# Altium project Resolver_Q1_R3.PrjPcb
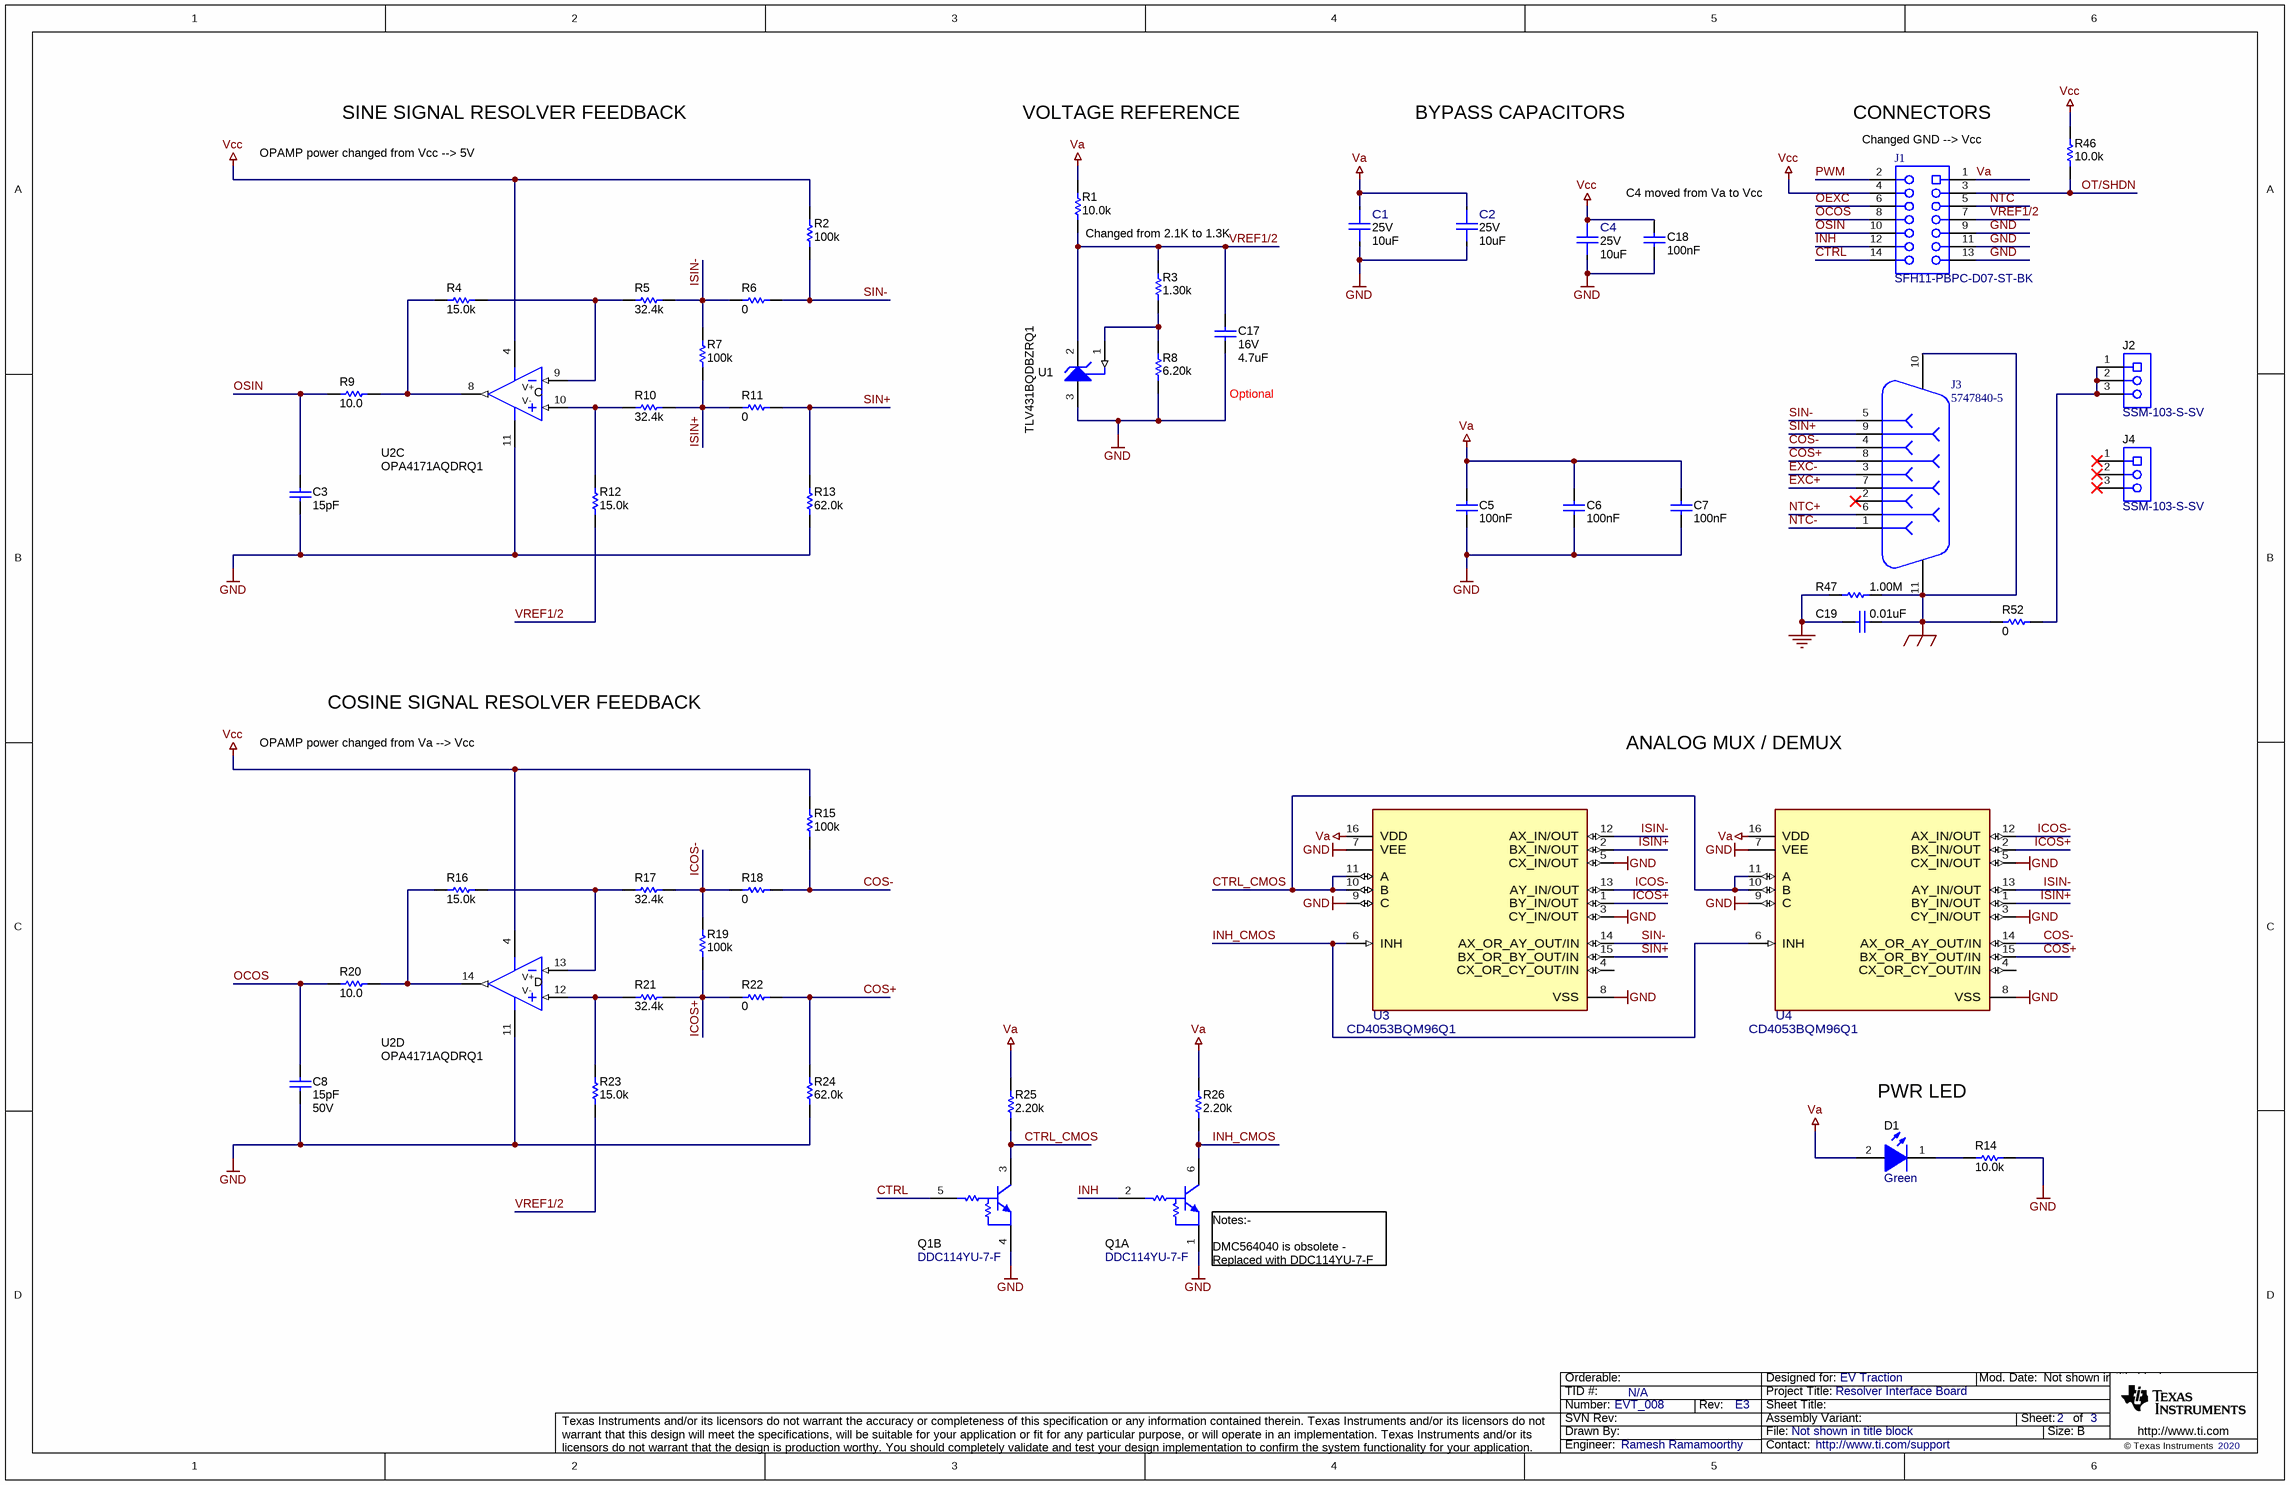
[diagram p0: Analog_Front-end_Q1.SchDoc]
CopyrightYear: 2020; PCB_Layout: Ramesh Ramamoorthy; PCB_Rev: E3; PRJ_Customer: EV Traction; PRJ_Engineer: Ramesh Ramamoorthy; PRJ_Number: EVT_008; PRJ_Title: Resolver Interface Board; SCH_Rev: E3; TechSupport: http://www.ti.com/support; TID: N/A
2 sheets, 102 parts. Net scope: global (net labels, ports and power ports of the same name join across sheets).
Board file: Resolver_Q1_R3.PcbDoc
Sheets:
  Analog_Front-end_Q1.SchDoc
  Excitation_Amplifier.SchDoc

## Sheet Analog_Front-end_Q1.SchDoc
size 431 x 279 mm; Date: Not shown in title block; ApprovedBy: Not shown in title block; CheckedBy: Not shown in title block; Author: Not shown in title block; CompanyName: Not shown in title block; Engineer: Not shown in title block; Organization: Not shown in title block; Address1: Not shown in title block; Address2: Not shown in title block; Address3: Not shown in title block; Address4: Not shown in title block; DocumentNumber: 2; Revision: Use project parameter SCH_Rev; SheetNumber: 2; SheetTotal: 3; PageSetup: Record=PageOptions¦CenterHorizontal=True¦CenterVertical=True¦PrintScale=1.00¦XCorrection=1.00¦YCorrection=1.00¦PrintKind=0¦BorderSize=5000000¦LeftOffset=0¦BottomOffset=0¦Orientation=2¦PaperLength=1000¦PaperWidth=1000¦Scale=100¦PaperSource=15¦PrintQuality=600¦MediaType=1¦DitherType=10¦PaperKind=Letter¦PrintScaleMode=1

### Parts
C1  VDC_V: 25V  ValueDisplayed: 10uF  [FP-CGA4J1X7S1E106K125AC_0805-MFG]  (hidden comment: CGA4J1X7S1E106K125AC)
C2  VDC_V: 25V  ValueDisplayed: 10uF  [FP-CGA4J1X7S1E106K125AC_0805-MFG]  (hidden comment: CGA4J1X7S1E106K125AC)
C3  ValueDisplayed: 15pF  [0603_HV]  (hidden comment: GRM1885C1H150JA01D)
C4  VDC_V: 25V  ValueDisplayed: 10uF  [FP-CGA4J1X7S1E106K125AC_0805-MFG]  (hidden comment: CGA4J1X7S1E106K125AC)
C5  Cap_F: 100nF  [0603_HV]  (hidden comment: GRM188R71E104KA01D)
C6  Cap_F: 100nF  [0603_HV]  (hidden comment: GRM188R71E104KA01D)
C7  Cap_F: 100nF  [0603_HV]  (hidden comment: GRM188R71E104KA01D)
C8  ValueDisplayed: 15pF  VDC_V: 50V  [0603_HV]  (hidden comment: GRM1885C1H150JA01D)
C17  VDC_V: 16V  ValueDisplayed: 4.7uF  [0603_HV]  (hidden comment: C1608X6S1C475K080AC)
C18  Cap_F: 100nF  [0603_HV]  (hidden comment: GRM188R71E104KA01D)
C19  ValueDisplayed: 0.01uF  [1206]  (hidden comment: 12061C103JAT2A)
D1  value Green  [WL-SMCW_GREEN]  (hidden comment: 150060GS75000)
J1  SFH11-PBPC-D07-ST-BK  [Sullins_SFH11-xxxC-D07-ST-BK]
J2  SSM-103-S-SV  [Samtec_SSM-103-x-SV]
J3  5747840-5  [TE_5747840-5]
J4  SSM-103-S-SV  [Samtec_SSM-103-x-SV]
Q1  DDC114YU-7-F  [SOT-363]  (parts A,B of 2)
R1  ValueDisplayed: 10.0k  [0603_HV]  (hidden comment: RC0603FR-0710KL)
R2  ValueDisplayed: 100k  [0603_HV]  (hidden comment: RC0603FR-07100KL)
R3  ValueDisplayed: 1.30k  [0603_HV]  (hidden comment: RC0603FR-071K3L)
R4  ValueDisplayed: 15.0k  [0603_HV]  (hidden comment: RC0603FR-0715KL)
R5  ValueDisplayed: 32.4k  [0603_HV]  (hidden comment: RC0603FR-0732K4L)
R6  ValueDisplayed: 0  [0603_HV]  (hidden comment: RC0603JR-070RL)
R7  ValueDisplayed: 100k  [0603_HV]  (hidden comment: RC0603FR-07100KL)
R8  ValueDisplayed: 6.20k  [0603_HV]  (hidden comment: RC0603FR-076K2L)
R9  ValueDisplayed: 10.0  [0603_HV]  (hidden comment: RC0603FR-0710RL)
R10  ValueDisplayed: 32.4k  [0603_HV]  (hidden comment: RC0603FR-0732K4L)
R11  ValueDisplayed: 0  [0603_HV]  (hidden comment: RC0603JR-070RL)
R12  ValueDisplayed: 15.0k  [0603_HV]  (hidden comment: RC0603FR-0715KL)
R13  ValueDisplayed: 62.0k  [0603_HV]  (hidden comment: RC0603FR-0762KL)
R14  ValueDisplayed: 10.0k  [0603_HV]  (hidden comment: RC0603FR-0710KL)
R15  ValueDisplayed: 100k  [0603_HV]  (hidden comment: RC0603FR-07100KL)
R16  ValueDisplayed: 15.0k  [0603_HV]  (hidden comment: RC0603FR-0715KL)
R17  ValueDisplayed: 32.4k  [0603_HV]  (hidden comment: RC0603FR-0732K4L)
R18  ValueDisplayed: 0  [0603_HV]  (hidden comment: RC0603JR-070RL)
R19  ValueDisplayed: 100k  [0603_HV]  (hidden comment: RC0603FR-07100KL)
R20  ValueDisplayed: 10.0  [0603_HV]  (hidden comment: RC0603FR-0710RL)
R21  ValueDisplayed: 32.4k  [0603_HV]  (hidden comment: RC0603FR-0732K4L)
R22  ValueDisplayed: 0  [0603_HV]  (hidden comment: RC0603JR-070RL)
R23  ValueDisplayed: 15.0k  [0603_HV]  (hidden comment: RC0603FR-0715KL)
R24  ValueDisplayed: 62.0k  [0603_HV]  (hidden comment: RC0603FR-0762KL)
R25  ValueDisplayed: 2.20k  [0603_HV]  (hidden comment: RC0603FR-072K2L)
R26  ValueDisplayed: 2.20k  [0603_HV]  (hidden comment: RC0603FR-072K2L)
R46  ValueDisplayed: 10.0k  [0603_HV]  (hidden comment: RC0603FR-0710KL)
R47  ValueDisplayed: 1.00M  [0402S]  (hidden comment: ERJ-2RKF1004X)
R52  ValueDisplayed: 0  [0603_HV]  (hidden comment: RC0603JR-070RL)
U1  TLV431BQDBZRQ1  [DBZ0003A_N]
U2  OPA4171AQDRQ1  [D0014A_L]  (parts C,D of 4)
U3  CD4053BQM96Q1  [D0016A-MFG]
U4  CD4053BQM96Q1  [D0016A-MFG]

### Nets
GND: C1.2 C2.2 C3.1 C4.2 C5.1 C6.1 C7.1 C8.1 C17.2 C18.1 C19.2 J1.9 J1.11 J1.13 Q1.1(E) Q1.4(E) R8.1 R13.1 R14.1 R24.1 R47.1 U1.3(ANODE) U2.11(V-) U3.3(CY_IN/OUT) U3.5(CX_IN/OUT) U3.7(VEE) U3.8(VSS) U3.9(C) U4.3(CY_IN/OUT) U4.5(CX_IN/OUT) U4.7(VEE) U4.8(VSS) U4.9(C)
SHIELD_GND: C19.1 J3.10 J3.11 R47.2 R52.2
Va: C1.1 C2.1 C5.2 C6.2 C7.2 D1.2(A) J1.1 R1.2 R25.2 R26.2 U3.16(VDD) U4.16(VDD)
Vcc: C4.1 C18.2 J1.4 R2.2 R15.2 R46.2 U2.4(V+)
COS+: J3.8 R22.1 R24.2 U4.15(BX_OR_BY_OUT/IN)
COS-: J3.4 R15.1 R18.1 U4.14(AX_OR_AY_OUT/IN)
CTRL: J1.14 Q1.5(B)
CTRL_CMOS: Q1.3(C) R25.1 U3.10(B) U3.11(A) U4.10(B) U4.11(A)
EXC+: J3.7
EXC-: J3.3
ICOS+: R19.1 R21.1 R22.2 U3.1(BY_IN/OUT) U4.2(BX_IN/OUT)
ICOS-: R17.1 R18.2 R19.2 U3.13(AY_IN/OUT) U4.12(AX_IN/OUT)
INH: J1.12 Q1.2(B)
INH_CMOS: Q1.6(C) R26.1 U3.6(INH) U4.6(INH)
ISIN+: R7.1 R10.1 R11.2 U3.2(BX_IN/OUT) U4.1(BY_IN/OUT)
ISIN-: R5.1 R6.2 R7.2 U3.12(AX_IN/OUT) U4.13(AY_IN/OUT)
NTC: J1.5
NTC+: J3.6
NTC-: J3.1
OCOS: C8.2 J1.8 R20.2
OEXC: J1.6
OSIN: C3.2 J1.10 R9.2
OT/SHDN: J1.3 R46.1
PWM: J1.2
SIN+: J3.9 R11.1 R13.2 U3.15(BX_OR_BY_OUT/IN)
SIN-: J3.5 R2.1 R6.1 U3.14(AX_OR_AY_OUT/IN)
VREF1/2: C17.1 J1.7 R1.1 R3.2 R12.1 R23.1 U1.2(CATHODE)
NetD1_1: D1.1(K) R14.2
NetJ2_1: J2.1 J2.2 J2.3 R52.1
NetR3_1: R3.1 R8.2 U1.1(REF)
NetR4_1: R4.1 R5.2 U2.9(IN-)
NetR4_2: R4.2 R9.1 U2.8(OUT)
NetR10_2: R10.2 R12.2 U2.10(IN+)
NetR16_1: R16.1 R17.2 U2.13(IN-)
NetR16_2: R16.2 R20.1 U2.14(OUT)
NetR21_2: R21.2 R23.2 U2.12(IN+)

Not connected (* = marked no-connect by the designer): J3 2*; J4 1* 2* 3*; U3 4(CX_OR_CY_OUT/IN); U4 4(CX_OR_CY_OUT/IN)

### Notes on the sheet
- OPAMP power changed from Vcc --> 5V
- SINE SIGNAL RESOLVER FEEDBACK
- VOLTAGE REFERENCE
- BYPASS CAPACITORS
- CONNECTORS
- (near J1) Changed GND --> Vcc
- (near R1) Changed from 2.1K to 1.3K
- C4 moved from Va to Vcc
- Optional
- COSINE SIGNAL RESOLVER FEEDBACK
- OPAMP power changed from Va --> Vcc
- ANALOG MUX / DEMUX
- PWR LED
- (near Q1) Notes:-
  DMC564040 is obsolete -
  Replaced with DDC114YU-7-F

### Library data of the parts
C1 C2 C4 = CMP-0091069-1: Cap Ceramic 10uF 25V X7S 10% Pad SMD 0805 +125°C Automotive T/R; Manufacturer: TDK Corporation; AEC Qualified: Yes; AEC Grade: Grade 1; Value: 10µF; Tolerance_%: 0.1%; SizeZ_mm: 1.45mm; TempCo: 22%
C3 = CMP-0007184-4: CAP, CERM, 15 pF, 50 V, +/- 5%, C0G/NP0, 0603; Manufacturer: MuRata; Polarized: N; Value: 15pF; U/M: EA; Value1: Unknown; VDC_V: 50V; TaMin_C: -55°C; TaMax_C: 125°C; Cap_Case: 0603; AEC Category: Q200; SizeArea_mm2: 1.28; SizeAreaWB_mm2: 4.68; SizeX_mm: 1.6; SizeY_mm: 0.8; SizeZ_mm: 1
C5-C7 C18 = CMP-0007404-4: CAP, CERM, 0.1 uF, 25 V, +/- 10%, X7R, 0603; Manufacturer: MuRata; Polarized: N; Value: 0.1uF; U/M: EA; Value1: Unknown; VDC_V: 25V; TaMin_C: -55°C; TaMax_C: 125°C; Cap_Case: 0603; AEC Category: Q200; SizeArea_mm2: 1.28; SizeAreaWB_mm2: 4.68; SizeX_mm: 1.6; SizeY_mm: 0.8; SizeZ_mm: 1
C8 = CMP-0007184-4: CAP, CERM, 15 pF, 50 V, +/- 5%, C0G/NP0, 0603; Manufacturer: MuRata; Polarized: N; Value: 15pF; U/M: EA; Value1: Unknown; TaMin_C: -55°C; TaMax_C: 125°C; Cap_Case: 0603; AEC Category: Q200; SizeArea_mm2: 1.28; SizeAreaWB_mm2: 4.68; SizeX_mm: 1.6; SizeY_mm: 0.8; SizeZ_mm: 1
C17 = CMP-0007028-3: CAP, CERM, 4.7 uF, 16 V, +/- 10%, X6S, 0603; Manufacturer: TDK; TaMin_C: -55°C; ESR_ohm: 3.728m; Polarized: N; SizeAreaWB_mm2: 4.68; Value1: 0.003728 ohm; U/M: EA; Value: 4.7uF; TaMax_C: 105°C; SizeZ_mm: 1; SizeX_mm: 1.6; SizeY_mm: 0.8; Cap_Case: 0603; SizeArea_mm2: 1.28; Cap_F: 4.7µF; IRMS_A: 2.69359A; AEC Category: Q200
C19 = CMP-0008484-2: CAP, CERM, 0.01 uF, 100 V, +/- 5%, X7R, 1206; Manufacturer: AVX; TaMin_C: -55°C; ESR_ohm: 1.19d; Polarized: N; SizeAreaWB_mm2: 10.92; Value1: 0.119 ohm; U/M: EA; Value: 0.01uF; TaMax_C: 125°C; SizeZ_mm: 1.35; SizeX_mm: 3.2; SizeY_mm: 1.6; Value2: 100V; SizeArea_mm2: 5.12; Cap_F: 10nF; AEC Category: Q200
D1 = CMP-0002905-2: LED, Green, SMD; Manufacturer: Wurth Elektronik; Type: InGaN; Vf_V: 3.2V; Io_A: 20mA; Tjmax_C: 85°C; Value1: W; Angle: 140
J1 = CMP-0054668-1: Receptacle, 2.54mm, 7x2, Gold, Black, TH; Manufacturer: Sullins Connector Solutions; CNHeader: FALSE; Current_A: 3A; Gender: Female; Voltage_V: 1kV; CompType: Socket Strip; Row_Count: 2; RowSpacing_mm: 2.54; CT: TRUE; Cert_UL: Y
J2 J4 = CMP-0078183-1: Receptacle, 2.54mm, 3x1, Gold with Tin tail, SMT; Manufacturer: Samtec; Pitch_mm: 2.54; Gender: Female; Cert_CSA: Y; Voltage_V: 405V; Current_A: 5.2A; Row_Count: 1; CompType: Socket Strip
J3 = CMP-0054938-2: D-Sub, 2.74mm, 9 Position, R/A, TH; Manufacturer: TE Connectivity; CNHeader: FALSE; Gender: Male; Row_Count: 2; Pitch_mm: 2.74; ContactFinish: Gold; CT: TRUE; Cert_UL: Y
Q1 = CMP-0000496-2: Transistor, Dual NPN, 50 V, 0.1 A, SOT-363; Manufacturer: Panasonic; PNP: 0; NPN: 2; Vceo_V: 50V; Vcesat1_V: 250mV; Value: 50 V; IcRated_A: 100mA; Value1: 0.1 A; TaMin_C: -40°C; TaMax_C: 85°C; SizeAreaWB_mm2: 10.24; SizeArea_mm2: 4.84; SizeX_mm: 2.2; SizeZ_mm: 1.1; CompType: BJT; U/M: EA; AEC Category: Q101; AEC Qualified: N
R1 R14 R46 = CMP-0022746-5: RES, 10.0 k, 1%, 0.1 W, 0603; Manufacturer: Yageo; Value: 10.0k; Res_ohm: 10k; Value_Code: 10k0; Power_W: 100mW; Value2: 0.1W; VDC_V: 75V; TempCo: 100 ppm/C; EIA_Code: E96; AEC Category: Q200; AEC Qualified: N; SizeArea_mm2: 1.28; SizeX_mm: 1.6; SizeY_mm: 0.8; SizeZ_mm: 1; SizeAreaWB_mm2: 4.68
R2 R7 R15 R19 = CMP-0022735-5: RES, 100 k, 1%, 0.1 W, 0603; Manufacturer: Yageo; Value: 100k; Power_W: 100mW; Value2: 0.1W; VDC_V: 75V; TempCo: 100 ppm/C; EIA_Code: E96; AEC Category: Q200; AEC Qualified: N; SizeArea_mm2: 1.28; SizeX_mm: 1.6; SizeY_mm: 0.8; SizeZ_mm: 1; SizeAreaWB_mm2: 4.68
R3 = CMP-0022877-5: RES, 1.30 k, 1%, 0.1 W, 0603; Manufacturer: Yageo; Power_W: 100mW; TempCo: 100 ppm/C; Value_Code: 1k30; Value: 1.30k; EIA_Code: E96; Res_ohm: 1.3k; SizeX_mm: 1.6; SizeY_mm: 0.8; SizeZ_mm: 1; Value2: 0.1W; SizeArea_mm2: 1.28; AEC Qualified: N; VDC_V: 75V; AEC Category: Q200; SizeAreaWB_mm2: 4.68
R4 R12 R16 R23 = CMP-0022816-5: RES, 15.0 k, 1%, 0.1 W, 0603; Manufacturer: Yageo; Value: 15.0k; Res_ohm: 15k; Value_Code: 15k0; Power_W: 100mW; Value2: 0.1W; VDC_V: 75V; TempCo: 100 ppm/C; EIA_Code: E96; AEC Category: Q200; AEC Qualified: N; SizeArea_mm2: 1.28; SizeX_mm: 1.6; SizeY_mm: 0.8; SizeZ_mm: 1; SizeAreaWB_mm2: 4.68
R5 R10 R17 R21 = CMP-0023030-5: RES, 32.4 k, 1%, 0.1 W, 0603; Manufacturer: Yageo; Value: 32.4k; Value_Code: 32k4; Power_W: 100mW; Value2: 0.1W; VDC_V: 75V; TempCo: 100 ppm/C; EIA_Code: E96; AEC Category: Q200; AEC Qualified: N; SizeArea_mm2: 1.28; SizeX_mm: 1.6; SizeY_mm: 0.8; SizeZ_mm: 1; SizeAreaWB_mm2: 4.68
R6 R11 R18 R22 R52 = CMP-0025885-5: RES, 0, 5%, 0.1 W, 0603; Manufacturer: Yageo; Value: 0; Value_Code: 0000; Power_W: 100mW; Value2: 0.1W; VDC_V: 75V; TempCo: 200 ppm/C; EIA_Code: E24; AEC Category: Q200; AEC Qualified: N; SizeArea_mm2: 1.28; SizeX_mm: 1.6; SizeY_mm: 0.8; SizeZ_mm: 1; SizeAreaWB_mm2: 4.68
R8 = CMP-0023248-5: RES, 6.20 k, 1%, 0.1 W, 0603; Manufacturer: Yageo; Value: 6.20k; Res_ohm: 6.2k; Value_Code: 6k20; Power_W: 100mW; Value2: 0.1W; VDC_V: 75V; TempCo: 100 ppm/C; AEC Category: Q200; AEC Qualified: N; SizeArea_mm2: 1.28; SizeX_mm: 1.6; SizeY_mm: 0.8; SizeZ_mm: 1; SizeAreaWB_mm2: 4.68
R9 R20 = CMP-0022751-4: RES, 10.0, 1%, 0.1 W, 0603; Manufacturer: Yageo; Value: 10.0; Res_ohm: 10; Value_Code: 10R0; Power_W: 100mW; Value2: 0.1W; VDC_V: 75V; TempCo: 100 ppm/C; EIA_Code: E96; AEC Category: Q200; AEC Qualified: N; SizeArea_mm2: 1.28; SizeX_mm: 1.6; SizeY_mm: 0.8; SizeZ_mm: 1; SizeAreaWB_mm2: 4.68
R13 R24 = CMP-0023220-5: RES, 62.0 k, 1%, 0.1 W, 0603; Manufacturer: Yageo; Value: 62.0k; Res_ohm: 62k; Value_Code: 62k0; Power_W: 100mW; Value2: 0.1W; VDC_V: 75V; TempCo: 100 ppm/C; AEC Category: Q200; AEC Qualified: N; SizeArea_mm2: 1.28; SizeX_mm: 1.6; SizeY_mm: 0.8; SizeZ_mm: 1; SizeAreaWB_mm2: 4.68
R25 R26 = CMP-0022986-5: RES, 2.20 k, 1%, 0.1 W, 0603; Manufacturer: Yageo; Value: 2.20k; Res_ohm: 2.2k; Value_Code: 2k20; Power_W: 100mW; Value2: 0.1W; VDC_V: 75V; TempCo: 100 ppm/C; AEC Category: Q200; AEC Qualified: N; SizeArea_mm2: 1.28; SizeX_mm: 1.6; SizeY_mm: 0.8; SizeZ_mm: 1; SizeAreaWB_mm2: 4.68
R47 = CMP-0026660-1: RES, 1.00 M, 1%, 0.1 W, 0402; Manufacturer: Panasonic; Power_W: 100mW; TempCo: 100 ppm/C; Value_Code: 1M00; U/M: EA; Value: 1.00Meg; EIA_Code: E96; Res_ohm: 1M; SizeX_mm: 1; SizeY_mm: 0.5; SizeZ_mm: 0.6; Value2: 0.1W; VDC_V: 50V; AEC Category: Q200
U1 = CMP-0033032-1: Automotive Catalog Low-Voltage Adjustable Precision Shunt Regulator, 15 mA, -40 to 125 degC, 3-pin SOT-23 (DBZ), Green (RoHS & no Sb/Br); Manufacturer: Texas Instruments; Iout/Iz(Max)(mA): 15; Min Iz for Regulation(uA): 80; SubFamily: Shunt Voltage Reference; VO Adj(Max)(V): 6; VO Adj(Min)(V): 1.24; Initial Accuracy @ 25/deg C(%): 0.5
U2 = CMP-0860035-1: Automotive Catalog 36V, Low Power, RRO, General Purpose Operational Amplifier, D0014A (SOIC-14); Manufacturer: Texas Instruments; AEC Category: Q200; AEC Qualified: Y; CompType: IC; SizeArea_mm2: 51.9; SizeAreaWB_mm2: 85.2; SizeX_mm: 6; SizeY_mm: 8.65; SizeZ_mm: 1.75
U3 U4 = CMP-0088292-1: 3 Circuit IC Switch 2:1 240Ohm 16-SOIC; Manufacturer: Texas Instruments; On State Resistance: 125Ω; -3Db Bandwith: 30MHz; AEC Qualified: Yes; TJmax_C: +150°C; Nominal Supply Current: 0.04-0.08uA; Standoff Height: 0.1mm; PositionCount: 3; AEC Grade: Grade 1; Max Supply Voltage: 20V; Min Supply Voltage: 3V; SizeZ_mm: 1.75mm

## Sheet Excitation_Amplifier.SchDoc
size 431 x 279 mm; Date: Not shown in title block; ApprovedBy: Not shown in title block; CheckedBy: Not shown in title block; Author: Not shown in title block; CompanyName: Not shown in title block; Engineer: Not shown in title block; Organization: Not shown in title block; Address1: Not shown in title block; Address2: Not shown in title block; Address3: Not shown in title block; Address4: Not shown in title block; DocumentNumber: 2; Revision: Use project parameter SCH_Rev; SheetNumber: 2; SheetTotal: 3; PageSetup: Record=PageOptions¦CenterHorizontal=True¦CenterVertical=True¦PrintScale=1.00¦XCorrection=1.00¦YCorrection=1.00¦PrintKind=0¦BorderSize=5000000¦LeftOffset=0¦BottomOffset=0¦Orientation=2¦PaperLength=1000¦PaperWidth=1000¦Scale=100¦PaperSource=15¦PrintQuality=600¦MediaType=1¦DitherType=10¦PaperKind=Letter¦PrintScaleMode=1
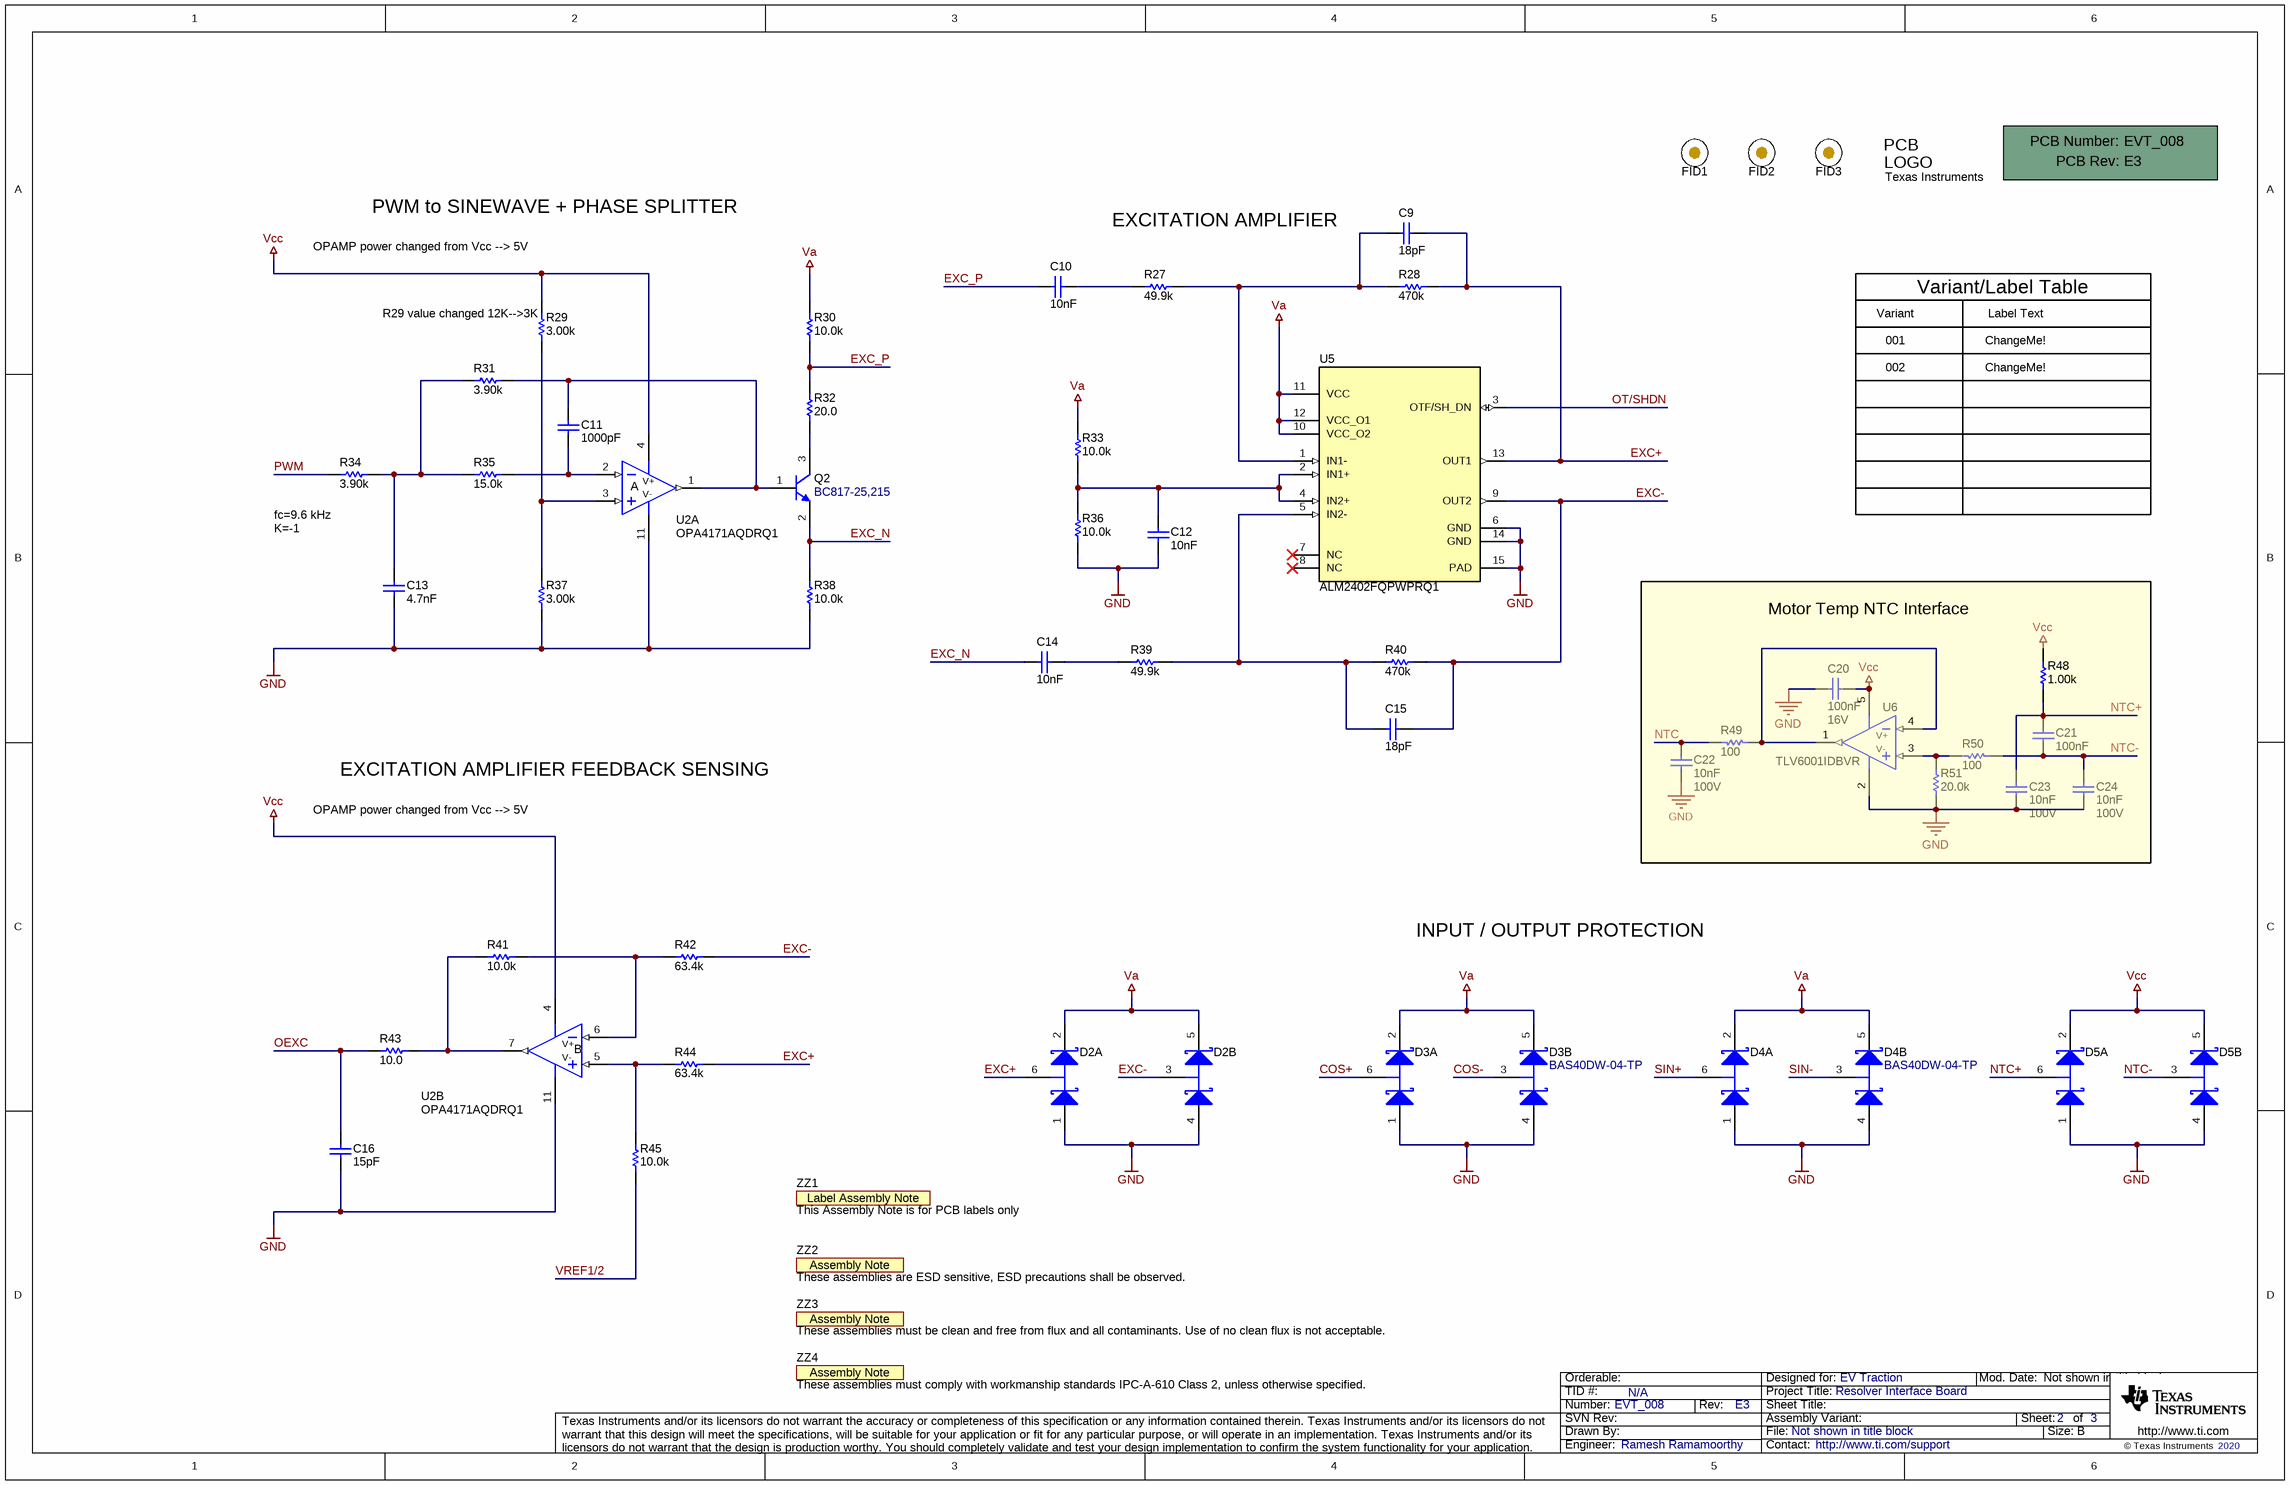
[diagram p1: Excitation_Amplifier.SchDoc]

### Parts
!PCB1  Printed Circuit Board  (value not drawn)  (mechanical)
C9  ValueDisplayed: 18pF  [0603_HV]  (hidden comment: GRM1885C1H180JA01D)
C10  Cap_F: 10nF  [0603_HV]  (hidden comment: GRM188R71H103KA01D)
C11  ValueDisplayed: 1000pF  [0603_HV]  (hidden comment: GRM1885C1H102JA01D)
C12  Cap_F: 10nF  [0603_HV]  (hidden comment: GRM188R71H103KA01D)
C13  Cap_F: 4.7nF  [0603_HV]  (hidden comment: GRM188R71H472KA01D)
C14  Cap_F: 10nF  [0603_HV]  (hidden comment: GRM188R71H103KA01D)
C15  ValueDisplayed: 18pF  [0603_HV]  (hidden comment: GRM1885C1H180JA01D)
C16  ValueDisplayed: 15pF  [0603_HV]  (hidden comment: GRM1885C1H150JA01D)
C20  Cap_F: 100nF  VDC_V: 16V  [0805_HV]  (hidden comment: GRM219R71C104KA01D)
C21  Cap_F: 100nF  [0603_HV]  (hidden comment: GRM188R71E104KA01D)
C22  Cap_F: 10nF  VDC_V: 100V  [0805_HV]  (hidden comment: 08051C103JAT2A)
C23  Cap_F: 10nF  VDC_V: 100V  [0805_HV]  (hidden comment: 08051C103JAT2A)
C24  Cap_F: 10nF  VDC_V: 100V  [0805_HV]  (hidden comment: 08051C103JAT2A)
D2  BAS40DW-04-TP  [SOT-363]  (value not drawn)  (parts A,B of 2)
D3  BAS40DW-04-TP  [SOT-363]  (value not drawn)  (parts A,B of 2)
D4  BAS40DW-04-TP  [SOT-363]  (value not drawn)  (parts A,B of 2)
D5  BAS40DW-04-TP  [SOT-363]  (value not drawn)  (parts A,B of 2)
FID1  Fiducial  [Fiducial10-20]  (value not drawn)
FID2  Fiducial  [Fiducial10-20]  (value not drawn)
FID3  Fiducial  [Fiducial10-20]  (value not drawn)
Logo1  Texas Instruments  [TI_Symbol_Overlay_Small]  (no BOM)
Q2  BC817-25,215  [SOT-23]
R27  ValueDisplayed: 49.9k  [0603_HV]  (hidden comment: RT0603BRD0749K9L)
R28  ValueDisplayed: 470k  [0603_HV]  (hidden comment: RC0603FR-07470KL)
R29  ValueDisplayed: 3.00k  [0603_HV]  (hidden comment: RC0603FR-073KL)
R30  ValueDisplayed: 10.0k  [0603_HV]  (hidden comment: RC0603FR-0710KL)
R31  ValueDisplayed: 3.90k  [0603_HV]  (hidden comment: RC0603FR-073K9L)
R32  ValueDisplayed: 20.0  [0603_HV]  (hidden comment: RC0603FR-0720RL)
R33  ValueDisplayed: 10.0k  [0603_HV]  (hidden comment: RC0603FR-0710KL)
R34  ValueDisplayed: 3.90k  [0603_HV]  (hidden comment: RC0603FR-073K9L)
R35  ValueDisplayed: 15.0k  [0603_HV]  (hidden comment: RC0603FR-0715KL)
R36  ValueDisplayed: 10.0k  [0603_HV]  (hidden comment: RC0603FR-0710KL)
R37  ValueDisplayed: 3.00k  [0603_HV]  (hidden comment: RC0603FR-073KL)
R38  ValueDisplayed: 10.0k  [0603_HV]  (hidden comment: RC0603FR-0710KL)
R39  ValueDisplayed: 49.9k  [0603_HV]  (hidden comment: RT0603BRD0749K9L)
R40  ValueDisplayed: 470k  [0603_HV]  (hidden comment: RC0603FR-07470KL)
R41  ValueDisplayed: 10.0k  [0603_HV]  (hidden comment: RC0603FR-0710KL)
R42  ValueDisplayed: 63.4k  [0603_HV]  (hidden comment: RC0603FR-0763K4L)
R43  ValueDisplayed: 10.0  [0603_HV]  (hidden comment: RC0603FR-0710RL)
R44  ValueDisplayed: 63.4k  [0603_HV]  (hidden comment: RC0603FR-0763K4L)
R45  ValueDisplayed: 10.0k  [0603_HV]  (hidden comment: RC0603FR-0710KL)
R48  ValueDisplayed: 1.00k  [0805_HV]  (hidden comment: ERJ-6ENF1001V)
R49  ValueDisplayed: 100  [0805_HV]  (hidden comment: CRCW0805100RDHEAP)
R50  ValueDisplayed: 100  [0805_HV]  (hidden comment: CRCW0805100RDHEAP)
R51  ValueDisplayed: 20.0k  [0805_HV]  (hidden comment: ERJ-6ENF2002V)
U2  OPA4171AQDRQ1  [D0014A_L]  (parts A,B of 4)
U5  ALM2402FQPWPRQ1  [PWP0014H_N]
U6  TLV6001IDBVR  [DBV0005A_N]
ZZ1  This Assembly Note is for PCB labels only  [AssemblyNoteLabel]  (no BOM)
ZZ2  These assemblies are ESD sensitive, ESD precautions shall be observed.  [AssemblyNote]  (no BOM)
ZZ3  These assemblies must be clean and free from flux and all contaminants. Use of no clean flux is not acceptable.  [AssemblyNote]  (no BOM)
ZZ4  These assemblies must comply with workmanship standards IPC-A-610 Class 2, unless otherwise specified.  [AssemblyNote]  (no BOM)

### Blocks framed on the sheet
Motor Temp NTC Interface: C20-C24 R48-R51 U6

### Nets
GND: C12.1 C13.1 C16.1 C20.2 C22.2 C23.2 C24.2 D2.1(A1) D2.4(A2) D3.1(A1) D3.4(A2) D4.1(A1) D4.4(A2) D5.1(A1) D5.4(A2) R36.1 R37.1 R38.1 R51.1 U2.11(V-) U5.6(GND) U5.14(GND) U5.15(PAD) U6.2(V-)
Va: D2.2(C1) D2.5(C2) D3.2(C1) D3.5(C2) D4.2(C1) D4.5(C2) R30.2 R33.2 U5.10(VCC_O2) U5.11(VCC) U5.12(VCC_O1)
Vcc: C20.1 D5.2(C1) D5.5(C2) R29.2 R48.2 U2.4(V+) U6.5(V+)
COS+: D3.6(AC1)
COS-: D3.3(AC2)
EXC+: C9.2 D2.6(AC1) R28.2 R44.1 U5.13(OUT1)
EXC-: C15.2 D2.3(AC2) R40.2 R42.1 U5.9(OUT2)
EXC_N: C14.1 Q2.2(E) R38.2
EXC_P: C10.1 R30.1 R32.2
NTC: C22.1 R49.2
NTC+: C21.2 C23.1 D5.6(AC1) R48.1
NTC-: C21.1 C24.1 D5.3(AC2) R50.1
OEXC: C16.2 R43.2
OT/SHDN: U5.3(OTF/SH_DN)
PWM: R34.2
SIN+: D4.6(AC1)
SIN-: D4.3(AC2)
VREF1/2: R45.1
NetC9_1: C9.1 R27.2 R28.1 U5.1(IN1-)
NetC10_2: C10.2 R27.1
NetC11_1: C11.1 R35.1 U2.2(IN-)
NetC11_2: C11.2 Q2.1(B) R31.1 U2.1(OUT)
NetC12_2: C12.2 R33.1 R36.2 U5.2(IN1+) U5.4(IN2+)
NetC13_2: C13.2 R31.2 R34.1 R35.2
NetC14_2: C14.2 R39.1
NetC15_1: C15.1 R39.2 R40.1 U5.5(IN2-)
NetQ2_3: Q2.3(C) R32.1
NetR29_1: R29.1 R37.2 U2.3(IN+)
NetR41_1: R41.1 R42.2 U2.6(IN-)
NetR41_2: R41.2 R43.1 U2.7(OUT)
NetR44_2: R44.2 R45.2 U2.5(IN+)
NetR49_1: R49.1 U6.1(OUT) U6.4(IN-)
NetR50_2: R50.2 R51.2 U6.3(IN+)

Not connected (* = marked no-connect by the designer): U5 7(NC)* 8(NC)*

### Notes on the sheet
- PWM to SINEWAVE + PHASE SPLITTER
- EXCITATION AMPLIFIER
- OPAMP power changed from Vcc --> 5V
- Variant/Label Table
- (near R29) R29 value changed 12K-->3K
- Variant
- 001
- 002
- Label Text
- ChangeMe!
- (near R34) fc=9.6 kHz
- K=-1
- EXCITATION AMPLIFIER FEEDBACK SENSING
- INPUT / OUTPUT PROTECTION

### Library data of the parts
!PCB1 = CMP-0003618-2: Manufacturer: Any; PartNumber: EVT_008
C9 C15 = CMP-0007190-4: CAP, CERM, 18 pF, 50 V, +/- 5%, C0G/NP0, 0603; Manufacturer: MuRata; Polarized: N; Value: 18pF; U/M: EA; Value1: Unknown; VDC_V: 50V; TaMin_C: -55°C; TaMax_C: 125°C; Cap_Case: 0603; SizeArea_mm2: 1.28; SizeAreaWB_mm2: 4.68; SizeX_mm: 1.6; SizeY_mm: 0.8; SizeZ_mm: 1; AEC Category: Q200
C10 C12 C14 = CMP-0007433-4: CAP, CERM, 0.01 uF, 50 V, +/- 10%, X7R, 0603; Manufacturer: MuRata; Polarized: N; Value: 0.01uF; U/M: EA; Value1: Unknown; VDC_V: 50V; TaMin_C: -55°C; TaMax_C: 125°C; Cap_Case: 0603; AEC Category: Q200; SizeArea_mm2: 1.28; SizeAreaWB_mm2: 4.68; SizeX_mm: 1.6; SizeY_mm: 0.8; SizeZ_mm: 1
C11 = CMP-0007173-4: CAP, CERM, 1000 pF, 50 V, +/- 5%, C0G/NP0, 0603; Manufacturer: MuRata; Polarized: N; Value: 1000pF; U/M: EA; Cap_F: 1nF; Value1: Unknown; VDC_V: 50V; TaMin_C: -55°C; TaMax_C: 125°C; Cap_Case: 0603; AEC Category: Q200; SizeArea_mm2: 1.28; SizeAreaWB_mm2: 4.68; SizeX_mm: 1.6; SizeY_mm: 0.8; SizeZ_mm: 1
C13 = CMP-0007456-4: CAP, CERM, 4700 pF, 50 V, +/- 10%, X7R, 0603; Manufacturer: MuRata; Polarized: N; Value: 4700pF; U/M: EA; Value1: Unknown; VDC_V: 50V; TaMin_C: -55°C; TaMax_C: 125°C; Cap_Case: 0603; AEC Category: Q200; SizeArea_mm2: 1.28; SizeAreaWB_mm2: 4.68; SizeX_mm: 1.6; SizeY_mm: 0.8; SizeZ_mm: 1
C16 = CMP-0007184-4: as C3 on sheet Analog_Front-end_Q1
C20 = CMP-0008209-1: CAP, CERM, 0.1 uF, 16 V, +/- 10%, X7R, 0805; Manufacturer: MuRata; TaMin_C: -55°C; Polarized: N; SizeAreaWB_mm2: 6.75; Value1: Unknown; U/M: EA; Value: 0.1uF; TaMax_C: 125°C; SizeZ_mm: 1.45; SizeX_mm: 2; SizeY_mm: 1.25; Cap_Case: 0805; SizeArea_mm2: 2.5; AEC Category: Q200
C21 = CMP-0007404-4: as C5 on sheet Analog_Front-end_Q1
C22-C24 = CMP-0007542-1: CAP, CERM, 0.01 uF, 100 V, +/- 5%, X7R, 0805; Manufacturer: AVX; TaMin_C: -55°C; ESR_ohm: 0.078; Polarized: N; SizeAreaWB_mm2: 6.75; Value1: 0.078 ohm; U/M: EA; Value: 0.01uF; TaMax_C: 125°C; SizeZ_mm: 1.45; SizeX_mm: 2; SizeY_mm: 1.25; Cap_Case: 0805; SizeArea_mm2: 2.5; AEC Category: Q200
D2-D5 = CMP-0028604-2: Diode, Schottky, 40 V, 0.2 A, SOT-363; Manufacturer: Micro Commercial Components; Vf_V: 1V; Value: 40V; Value1: 0.2A; Io_A: 200mA; TJmax_C: 125°C; SizeAreaWB_mm2: 10.24; SizeArea_mm2: 4.84; SizeX_mm: 2.2; SizeZ_mm: 1.1; AEC Category: Q101; Green_Lifecycle: Not Set; Green_REACh: Incomplete
FID1-FID3 = CMP-0077181-1: Fiducial mark.  There is nothing to buy or mount.
Logo1 = CMP-0074838-1: Texas Instrument Corporate Signature; SymbolCreator: a0412235; Lib Reference: TI_Logo; Library Reference: Logo
Q2 = CMP-0000480-2: Transistor, NPN, 45 V, 0.5 A, SOT-23; Manufacturer: NXP Semiconductor; CompType: BJT; PNP: 0; NPN: 1; Vceo_V: 45V; Vcesat1_V: 700mV; Value: 45 V; IcRated_A: 500mA; Value1: 0.5 A; HfeMax: 400; TaMin_C: -65°C; TaMax_C: 150°C; SizeAreaWB_mm2: 14; SizeArea_mm2: 7.5; SizeX_mm: 2.5; SizeY_mm: 3; SizeZ_mm: 1.1; U/M: EA; AEC Category: Q101; AEC Qualified: N
R27 R39 = CMP-0024283-1: RES, 49.9 k, 0.1%, 0.1 W, 0603; Manufacturer: Yageo America; Power_W: 100mW; TempCo: 25 ppm/C; Value_Code: 49k9; U/M: EA; Value: 49.9k; EIA_Code: E192; SizeX_mm: 1.6; SizeY_mm: 0.8; SizeZ_mm: 1; Value2: 0.1W; SizeArea_mm2: 1.28; VDC_V: 75V; AEC Category: Q200
R28 R40 = CMP-0023128-4: RES, 470 k, 1%, 0.1 W, 0603; Manufacturer: Yageo; Value: 470k; Power_W: 100mW; Value2: 0.1W; VDC_V: 75V; TempCo: 100 ppm/C; AEC Category: Q200; AEC Qualified: N; SizeArea_mm2: 1.28; SizeX_mm: 1.6; SizeY_mm: 0.8; SizeZ_mm: 1; SizeAreaWB_mm2: 4.68
R29 R37 = CMP-0023091-5: RES, 3.00 k, 1%, 0.1 W, 0603; Manufacturer: Yageo; Value: 3.00k; Res_ohm: 3k; Value_Code: 3k00; Power_W: 100mW; Value2: 0.1W; VDC_V: 75V; TempCo: 100 ppm/C; AEC Category: Q200; AEC Qualified: N; SizeArea_mm2: 1.28; SizeX_mm: 1.6; SizeY_mm: 0.8; SizeZ_mm: 1; SizeAreaWB_mm2: 4.68
R30 R33 R36 R38 R41 R45 = CMP-0022746-5: as R1 on sheet Analog_Front-end_Q1
R31 R34 = CMP-0023090-5: RES, 3.90 k, 1%, 0.1 W, 0603; Manufacturer: Yageo; Value: 3.90k; Res_ohm: 3.9k; Value_Code: 3k90; Power_W: 100mW; Value2: 0.1W; VDC_V: 75V; TempCo: 100 ppm/C; AEC Category: Q200; AEC Qualified: N; SizeArea_mm2: 1.28; SizeX_mm: 1.6; SizeY_mm: 0.8; SizeZ_mm: 1; SizeAreaWB_mm2: 4.68
R32 = CMP-0022908-4: RES, 20.0, 1%, 0.1 W, 0603; Manufacturer: Yageo; Value: 20.0; Res_ohm: 20; Value_Code: 20R0; Power_W: 100mW; Value2: 0.1W; VDC_V: 75V; TempCo: 100 ppm/C; EIA_Code: E96; AEC Category: Q200; AEC Qualified: N; SizeArea_mm2: 1.28; SizeX_mm: 1.6; SizeY_mm: 0.8; SizeZ_mm: 1; SizeAreaWB_mm2: 4.68
R35 = CMP-0022816-5: as R4 on sheet Analog_Front-end_Q1
R42 R44 = CMP-0023224-5: RES, 63.4 k, 1%, 0.1 W, 0603; Manufacturer: Yageo; Value: 63.4k; Value_Code: 63k4; Power_W: 100mW; Value2: 0.1W; VDC_V: 75V; TempCo: 100 ppm/C; EIA_Code: E96; AEC Category: Q200; AEC Qualified: N; SizeArea_mm2: 1.28; SizeX_mm: 1.6; SizeY_mm: 0.8; SizeZ_mm: 1; SizeAreaWB_mm2: 4.68
R43 = CMP-0022751-4: as R9 on sheet Analog_Front-end_Q1
R48 = CMP-0021519-3: RES, 1.00 k, 1%, 0.125 W, AEC-Q200 Grade 0, 0805; Manufacturer: Panasonic; Power_W: 125mW; TempCo: 100 ppm/C; Value_Code: 1k00; Value: 1.00k; EIA_Code: E96; Res_ohm: 1k; SizeX_mm: 2; SizeY_mm: 1.25; SizeZ_mm: 1.45; Value2: 0.125W; SizeArea_mm2: 2.5; AEC Qualified: Y; AEC Category: Q200; AEC Grade: 0; SizeAreaWB_mm2: 6.75
R49 R50 = CMP-0065350-1: RES, 100, .5%, .125 W, AEC-Q200 Grade 0, 0805; Manufacturer: Vishay-Dale; Power_W: 125mW; TempCo: 50 ppm/C; Value_Code: 100R; U/M: EA; Value: 100; EIA_Code: E192; Tolerance_%: 0.5%; SizeX_mm: 2.0; SizeY_mm: 1.25; SizeZ_mm: 1.45; Value2: .125W; SizeArea_mm2: 2.5; AEC Qualified: Y; AEC Grade: 0; AEC Category: Q200
R51 = CMP-0021614-3: RES, 20.0 k, 1%, 0.125 W, AEC-Q200 Grade 0, 0805; Manufacturer: Panasonic; Power_W: 125mW; TempCo: 100 ppm/C; Value_Code: 20k0; Value: 20.0k; EIA_Code: E96; Res_ohm: 20k; SizeX_mm: 2; SizeY_mm: 1.25; SizeZ_mm: 1.45; Value2: 0.125W; SizeArea_mm2: 2.5; AEC Qualified: Y; AEC Category: Q200; AEC Grade: 0; SizeAreaWB_mm2: 6.75
U2 = CMP-0860035-1: as U2 on sheet Analog_Front-end_Q1
U5 = CMP-0081971-2: Dual Opamp with High Current Output, PWP0014H (HTSSOP-14); Alternate Manufacturer: Texas Instruments; SizeAreaWB_mm2: 58.8; SizeZ_mm: 1.2; SizeX_mm: 6.4; SizeY_mm: 5; SizeArea_mm2: 32; CompType: IC; AEC Qualified: Y; AEC Category: Q200
U6 = CMP-0073547-1: 1-MHz, Low-Power Operational Amplifier for Cost-Sensitive Systems, DBV0005A (SOT-23-5); Alternate PartNumber: TLV6001IDBVT; Alternate Manufacturer: Texas Instruments; SizeAreaWB_mm2: 14.82; U/M: EA; SizeZ_mm: 1.45; SizeX_mm: 2.8; SizeY_mm: 2.9; SizeArea_mm2: 8.12; CompType: IC
ZZ1 = CMP-0003616-3
ZZ2 = CMP-0077236-1
ZZ3 = CMP-0077237-1
ZZ4 = CMP-0077238-1

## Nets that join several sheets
GND: Analog_Front-end_Q1 (33 pins), Excitation_Amplifier (24 pins)
Va: Analog_Front-end_Q1 (12 pins), Excitation_Amplifier (11 pins)
Vcc: Analog_Front-end_Q1 (7 pins), Excitation_Amplifier (7 pins)
COS+: Analog_Front-end_Q1 (J3.8 R22.1 R24.2 U4.15), Excitation_Amplifier (D3.6)
COS-: Analog_Front-end_Q1 (J3.4 R15.1 R18.1 U4.14), Excitation_Amplifier (D3.3)
EXC+: Analog_Front-end_Q1 (J3.7), Excitation_Amplifier (5 pins)
EXC-: Analog_Front-end_Q1 (J3.3), Excitation_Amplifier (5 pins)
NTC: Analog_Front-end_Q1 (J1.5), Excitation_Amplifier (C22.1 R49.2)
NTC+: Analog_Front-end_Q1 (J3.6), Excitation_Amplifier (C21.2 C23.1 D5.6 R48.1)
NTC-: Analog_Front-end_Q1 (J3.1), Excitation_Amplifier (C21.1 C24.1 D5.3 R50.1)
OEXC: Analog_Front-end_Q1 (J1.6), Excitation_Amplifier (C16.2 R43.2)
OT/SHDN: Analog_Front-end_Q1 (J1.3 R46.1), Excitation_Amplifier (U5.3)
PWM: Analog_Front-end_Q1 (J1.2), Excitation_Amplifier (R34.2)
SIN+: Analog_Front-end_Q1 (J3.9 R11.1 R13.2 U3.15), Excitation_Amplifier (D4.6)
SIN-: Analog_Front-end_Q1 (J3.5 R2.1 R6.1 U3.14), Excitation_Amplifier (D4.3)
VREF1/2: Analog_Front-end_Q1 (7 pins), Excitation_Amplifier (R45.1)

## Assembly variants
001: not fitted C19 FID1 FID2 FID3 R2 R6 R11 R13 R15 R18 R22 R24 R47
